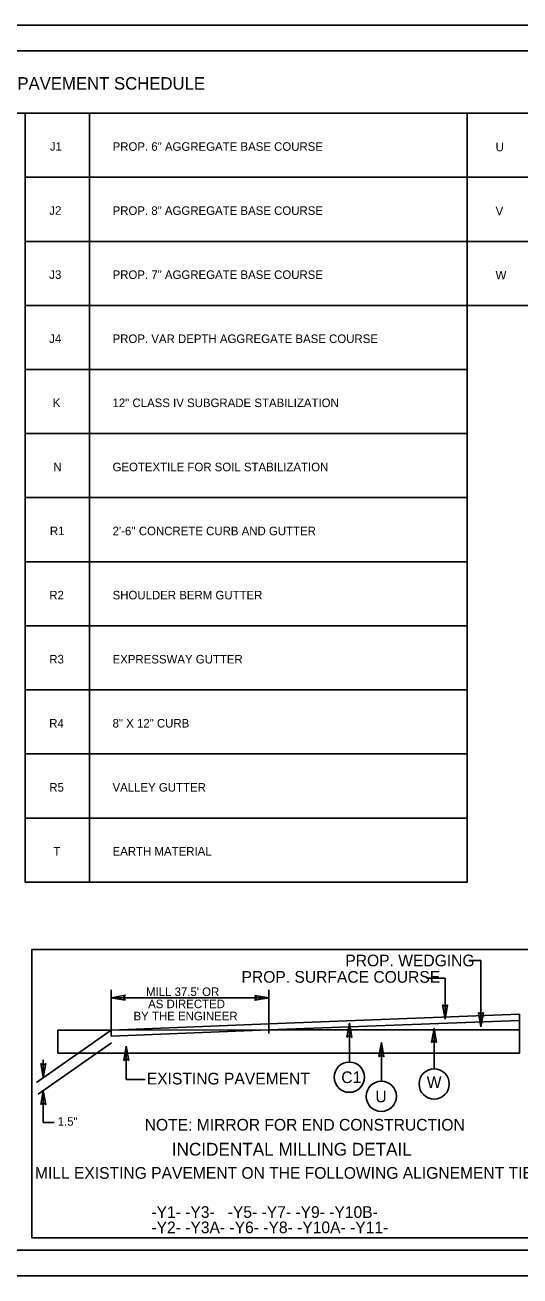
# Model space of a CAD drawing. Extents: x 18938 to 19565, y 6931 to 7973.
# Drawn here: x 19251.5 to 19309.4, y 7813.3 to 7959.7 of the extents above; entities that cross this region are included whole.
import ezdxf

# ---------------------------------------------------------------- set-up
doc = ezdxf.new("R2010")
doc.units = 0
for name, color, linetype in [('Old_Level_2', 7, 'Continuous'), ('Prop Dimension', 7, 'Continuous'), ('Prop Terminator CELL', 7, 'Continuous'), ('Sheet Typical CELL', 7, 'Continuous'), ('Typical Bridge Rail CELL', 7, 'Continuous'), ('Typical Curb CELL', 7, 'Continuous'), ('Typical Hinge Slope Arterial CELL', 7, 'Continuous'), ('Typical ID Circle CELL', 7, 'Continuous'), ('Typical Pavement Slope CELL', 7, 'Continuous'), ('Typical Pavement Slope Information CELL', 7, 'Continuous'), ('Typical Shoulder Slope Information CELL', 7, 'Continuous'), ('Typical Terminator CELL', 7, 'Continuous'), ('Typical Text General CELL', 7, 'Continuous'), ('Typical Text ID Circle CELL', 7, 'Continuous')]:
    doc.layers.add(name, color=color, linetype=linetype)

msp = doc.modelspace()

# ---------------------------------------------------------------- linework, layer by layer
at = {"layer": 'Old_Level_2'}
for p, q in [((19304.86, 7850.2), (19304.86, 7842.45)), ((19300.66, 7848.15), (19300.66, 7843.35)), ((19261.6, 7841.37), (19261.6, 7846.76)), ((19280.04, 7841.68), (19280.04, 7846.76)), ((19263.34, 7836.28), (19263.34, 7840.2)), ((19263.34, 7836.28), (19265.58, 7836.28))]:
    msp.add_line(p, q, dxfattribs=at)
msp.add_lwpolyline([(19252.31, 7817.75), (19313.57, 7817.75), (19313.57, 7851.51), (19252.31, 7851.51)], close=True, dxfattribs=at)
at = {"layer": 'Prop Dimension'}
msp.add_lwpolyline([(19155.17, 7813.28), (19382.43, 7813.28), (19382.43, 7959.71), (19155.17, 7959.71)], close=True, dxfattribs=at)
at = {"layer": 'Sheet Typical CELL'}
for p, q in [((19303.43, 7850.2), (19304.86, 7850.2)), ((19298.49, 7848.15), (19300.66, 7848.15)), ((19261.6, 7842.07), (19252.84, 7835.94)), ((19261.62, 7840.57), (19253.05, 7834.58)), ((19253.64, 7838.58), (19253.64, 7836.5)), ((19253.64, 7834.99), (19253.64, 7831.25)), ((19254.93, 7831.25), (19253.64, 7831.25))]:
    msp.add_line(p, q, dxfattribs=at)
at = {"layer": 'Typical Bridge Rail CELL'}
msp.add_line((19299.37, 7837.52), (19299.37, 7842.26), dxfattribs=at)
at = {"layer": 'Typical Curb CELL'}
for p, q in [((19300.37, 7845.03), (19300.66, 7843.35)), ((19300.66, 7844.81), (19300.37, 7845.03)), ((19300.66, 7843.35), (19300.96, 7845.03)), ((19300.96, 7845.03), (19300.66, 7844.81)), ((19304.57, 7844.14), (19304.86, 7842.45)), ((19304.86, 7843.92), (19304.57, 7844.14)), ((19304.86, 7842.45), (19305.16, 7844.13)), ((19305.16, 7844.13), (19304.86, 7843.92)), ((19263.05, 7838.52), (19263.34, 7840.2)), ((19263.34, 7840.2), (19263.65, 7838.52)), ((19263.35, 7838.74), (19263.05, 7838.52)), ((19263.65, 7838.52), (19263.35, 7838.74))]:
    msp.add_line(p, q, dxfattribs=at)
at = {"layer": 'Typical Hinge Slope Arterial CELL'}
for p, q in [((19309.39, 7843.91), (19280.04, 7842.79)), ((19280.04, 7842.1), (19309.39, 7843.18)), ((19309.39, 7842.08), (19309.39, 7843.91)), ((19280.04, 7842.79), (19261.6, 7842.07)), ((19261.6, 7841.37), (19280.04, 7842.1)), ((19261.6, 7842.07), (19261.6, 7842.07)), ((19261.6, 7842.07), (19261.6, 7841.37)), ((19280.04, 7842.79), (19280.04, 7842.1)), ((19280.04, 7842.1), (19280.04, 7842.79)), ((19280.04, 7842.1), (19309.39, 7842.08))]:
    msp.add_line(p, q, dxfattribs=at)
at = {"layer": 'Typical ID Circle CELL'}
for p, q in [((19261.6, 7842.07), (19255.34, 7842.07)), ((19255.34, 7842.07), (19255.34, 7839.38)), ((19261.6, 7842.07), (19280.04, 7842.1)), ((19309.39, 7842.08), (19309.39, 7839.38)), ((19309.39, 7839.38), (19255.34, 7839.38))]:
    msp.add_line(p, q, dxfattribs=at)
at = {"layer": 'Typical Pavement Slope CELL'}
msp.add_lwpolyline([(19177.64, 7956.71), (19345.58, 7956.71), (19345.58, 7949.39), (19177.64, 7949.39)], close=True, dxfattribs=at)
for points in [[(19259.05, 7941.89), (19251.5, 7941.89), (19251.5, 7949.39), (19303.26, 7949.39), (19303.26, 7941.89), (19259.05, 7941.89), (19259.05, 7949.39)], [(19310.81, 7941.89), (19303.26, 7941.89), (19303.26, 7949.39), (19345.58, 7949.39), (19345.58, 7941.89), (19310.81, 7941.89), (19310.81, 7949.39)], [(19259.05, 7934.39), (19251.5, 7934.39), (19251.5, 7941.89), (19303.26, 7941.89), (19303.26, 7934.39), (19259.05, 7934.39), (19259.05, 7941.89)], [(19310.81, 7934.39), (19303.26, 7934.39), (19303.26, 7941.89), (19345.58, 7941.89), (19345.58, 7934.39), (19310.81, 7934.39), (19310.81, 7941.89)], [(19259.05, 7926.89), (19251.5, 7926.89), (19251.5, 7934.39), (19303.26, 7934.39), (19303.26, 7926.89), (19259.05, 7926.89), (19259.05, 7934.39)], [(19310.81, 7926.89), (19303.26, 7926.89), (19303.26, 7934.39), (19345.58, 7934.39), (19345.58, 7926.89), (19310.81, 7926.89), (19310.81, 7934.39)], [(19259.05, 7919.39), (19251.5, 7919.39), (19251.5, 7926.89), (19303.26, 7926.89), (19303.26, 7919.39), (19259.05, 7919.39), (19259.05, 7926.89)], [(19259.05, 7911.89), (19251.5, 7911.89), (19251.5, 7919.39), (19303.26, 7919.39), (19303.26, 7911.89), (19259.05, 7911.89), (19259.05, 7919.39)], [(19259.05, 7904.39), (19251.5, 7904.39), (19251.5, 7911.89), (19303.26, 7911.89), (19303.26, 7904.39), (19259.05, 7904.39), (19259.05, 7911.89)], [(19259.05, 7896.89), (19251.5, 7896.89), (19251.5, 7904.39), (19303.26, 7904.39), (19303.26, 7896.89), (19259.05, 7896.89), (19259.05, 7904.39)], [(19259.05, 7889.39), (19251.5, 7889.39), (19251.5, 7896.89), (19303.26, 7896.89), (19303.26, 7889.39), (19259.05, 7889.39), (19259.05, 7896.89)], [(19259.05, 7881.89), (19251.5, 7881.89), (19251.5, 7889.39), (19303.26, 7889.39), (19303.26, 7881.89), (19259.05, 7881.89), (19259.05, 7889.39)], [(19259.05, 7874.39), (19251.5, 7874.39), (19251.5, 7881.89), (19303.26, 7881.89), (19303.26, 7874.39), (19259.05, 7874.39), (19259.05, 7881.89)], [(19259.05, 7866.89), (19251.5, 7866.89), (19251.5, 7874.39), (19303.26, 7874.39), (19303.26, 7866.89), (19259.05, 7866.89), (19259.05, 7874.39)], [(19259.05, 7859.39), (19251.5, 7859.39), (19251.5, 7866.89), (19303.26, 7866.89), (19303.26, 7859.39), (19259.05, 7859.39), (19259.05, 7866.89)]]:
    msp.add_lwpolyline(points, dxfattribs=at)
at = {"layer": 'Typical Pavement Slope Information CELL'}
msp.add_lwpolyline([(19380.14, 7956.71), (19177.64, 7956.71), (19177.64, 7816.29), (19380.14, 7816.29)], close=True, dxfattribs=at)
at = {"layer": 'Typical Shoulder Slope Information CELL'}
for p, q in [((19309.39, 7843.91), (19280.04, 7842.79)), ((19280.04, 7842.1), (19309.39, 7843.18)), ((19309.39, 7843.18), (19280.04, 7842.1)), ((19309.39, 7843.18), (19309.39, 7843.91)), ((19309.39, 7842.08), (19309.39, 7843.18)), ((19280.04, 7842.79), (19261.6, 7842.07)), ((19261.6, 7841.37), (19280.04, 7842.1)), ((19261.6, 7842.07), (19261.6, 7841.37)), ((19280.04, 7842.79), (19280.04, 7842.1)), ((19280.04, 7842.1), (19309.39, 7842.08))]:
    msp.add_line(p, q, dxfattribs=at)
at = {"layer": 'Typical Terminator CELL'}
for p, q in [((19280.04, 7845.85), (19261.6, 7845.85)), ((19289.46, 7838.32), (19289.46, 7842.86)), ((19293.21, 7836.07), (19293.21, 7840.61))]:
    msp.add_line(p, q, dxfattribs=at)
for centre in [(19289.46, 7836.55), (19299.39, 7835.76), (19293.2, 7834.31)]:
    msp.add_circle(centre, 1.77, dxfattribs=at)
at = {"layer": 'Typical Text General CELL'}
for points in [[(19263.23, 7845.57), (19261.6, 7845.85), (19263.24, 7846.14), (19263.03, 7845.85)], [(19278.4, 7846.13), (19280.04, 7845.85), (19278.4, 7845.56), (19278.6, 7845.85)], [(19289.18, 7841.22), (19289.46, 7842.86), (19289.75, 7841.21), (19289.46, 7841.42)], [(19299.09, 7840.63), (19299.37, 7842.26), (19299.66, 7840.62), (19299.37, 7840.83)], [(19292.93, 7838.98), (19293.21, 7840.61), (19293.5, 7838.97), (19293.21, 7839.18)], [(19253.36, 7838.14), (19253.64, 7836.5), (19253.93, 7838.15), (19253.64, 7837.94)], [(19253.36, 7833.35), (19253.64, 7834.99), (19253.93, 7833.34), (19253.64, 7833.55)]]:
    msp.add_lwpolyline(points, close=True, dxfattribs=at)

# ---------------------------------------------------------------- texts
at = {"layer": 'Old_Level_2'}
for s, p in [('PROP. WEDGING', (19288.99, 7849.53)), ('PROP. SURFACE COURSE ', (19276.84, 7847.61)), ('EXISTING PAVEMENT', (19265.75, 7835.7))]:
    msp.add_text(s, height=1.3666, dxfattribs=at).set_placement(p)
at = {"layer": 'Prop Terminator CELL'}
for s, height, p in [('C1', 1.367, (19288.52, 7835.86)), ('U', 1.37, (19292.51, 7833.61))]:
    msp.add_text(s, height=height, rotation=0.0001, dxfattribs=at).set_placement(p)
at = {"layer": 'Sheet Typical CELL'}
for s, height, p in [("MILL 37.5' OR ", 1, (19265.66, 7846.05)), ('AS DIRECTED ', 1, (19265.91, 7844.63)), ('BY THE ENGINEER', 1, (19264.2, 7843.21)), ('1.5"', 1, (19255.32, 7830.87)), ('NOTE: MIRROR FOR END CONSTRUCTION', 1.3666, (19265.51, 7830.3)), ('MILL EXISTING PAVEMENT ON THE FOLLOWING ALIGNEMENT TIES:', 1.3666, (19252.66, 7824.66)), ('-Y1- -Y3-   -Y5- -Y7- -Y9- -Y10B-', 1.3666, (19266.29, 7820.08)), ('-Y2- -Y3A- -Y6- -Y8- -Y10A- -Y11-', 1.3666, (19266.29, 7818.29))]:
    msp.add_text(s, height=height, dxfattribs=at).set_placement(p)
at = {"layer": 'Typical Pavement Slope CELL'}
for s, height, p in [('FINAL PAVEMENT SCHEDULE', 1.4632, (19244.52, 7952.15)), ('J1', 1, (19254.41, 7945)), ('PROP. 6" AGGREGATE BASE COURSE', 1, (19261.75, 7944.99)), ('U', 1, (19306.58, 7944.93)), ('J2', 1, (19254.34, 7937.5)), ('PROP. 8" AGGREGATE BASE COURSE', 1, (19261.75, 7937.49)), ('V', 1, (19306.58, 7937.44)), ('J3', 1, (19254.34, 7930)), ('PROP. 7" AGGREGATE BASE COURSE', 1, (19261.75, 7929.99)), ('W', 1, (19306.58, 7929.94)), ('J4', 1, (19254.33, 7922.5)), ('PROP. VAR DEPTH AGGREGATE BASE COURSE', 1, (19261.75, 7922.49)), ('K', 1, (19254.75, 7915)), ('12" CLASS IV SUBGRADE STABILIZATION', 1, (19261.74, 7914.99)), ('N', 1, (19254.82, 7907.48)), ('GEOTEXTILE FOR SOIL STABILIZATION', 1, (19261.74, 7907.48)), ('R1', 1, (19254.41, 7900)), ("2'-6'' CONCRETE CURB AND GUTTER", 1, (19261.75, 7899.99)), ('R2', 1, (19254.34, 7892.48)), ('SHOULDER BERM GUTTER', 1, (19261.75, 7892.48)), ('R3', 1, (19254.34, 7884.98)), ('EXPRESSWAY GUTTER', 1, (19261.75, 7884.98)), ('R4', 1, (19254.33, 7877.48)), ('8" X 12" CURB', 1, (19261.75, 7877.48)), ('R5', 1, (19254.34, 7869.98)), ('VALLEY GUTTER', 1, (19261.74, 7869.98)), ('T', 1, (19254.82, 7862.5)), ('EARTH MATERIAL', 1, (19261.75, 7862.5))]:
    msp.add_text(s, height=height, dxfattribs=at).set_placement(p)
at = {"layer": 'Typical Shoulder Slope Information CELL'}
msp.add_text('INCIDENTAL MILLING DETAIL', height=1.5, dxfattribs=at).set_placement((19268.68, 7827.37))
at = {"layer": 'Typical Text ID Circle CELL'}
msp.add_text('W', height=1.37, dxfattribs=at).set_placement((19298.52, 7835.28))

doc.saveas('drawing.dxf')
